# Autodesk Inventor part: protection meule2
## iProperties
Shininess: 64.0
Length Units: 11269
Angle Units: 11279
Time Units: 11290
Mass Units: 11283
Length Display Precision: 3
Angle Display Precision: 2
Compacted: True
Part Number: protection meule2
Document SubType Name: Modeling
Created: 2005-01
Material: Par défaut
Designer: LEGERET Philippe
Density: 0.0
Volumn: 0.0
Area: 0.0
PropertySet Name: Model Information
Control State: 0
Master: False
Checked Out: False
Author: LEGERET Philippe
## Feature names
1. Extrusion1
2. Extrusion2
3. Extrusion3
